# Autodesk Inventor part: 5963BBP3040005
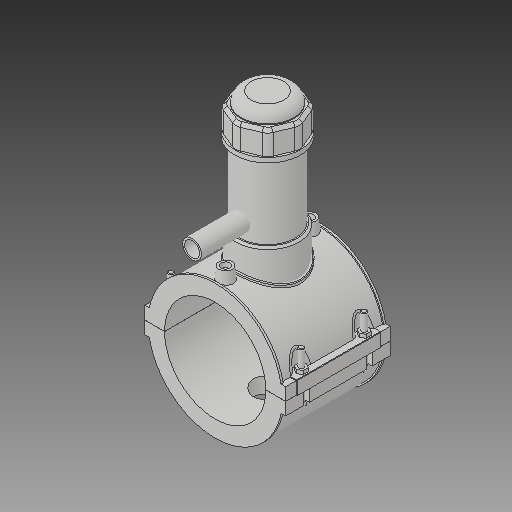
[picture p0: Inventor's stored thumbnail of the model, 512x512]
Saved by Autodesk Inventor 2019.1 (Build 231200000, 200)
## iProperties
Created: 2017-07
Part Number: 5963BBP3040005
Material: Generic
Description: PLASSON TAPPING SADDLE 4''IPS x 1/2''IPS
Document SubType Name: Modeling
Designer: KIM
Density: 1 g/cm^3
Appearance: Default
Author: KIM
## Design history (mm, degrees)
derived "5963BBP_5963BUP.ipt"
feature "Solid1::5963BBP_5963BUP.ipt"
feature "Solid2::5963BBP_5963BUP.ipt"
feature "Solid3::5963BBP_5963BUP.ipt"
tag "TaggingFeature1"
body "Solid1"
body "Solid2"
body "Solid3"
other parameters: "d0" = 114.1, "d2" = 159.004, "d3" = 28.525, "d4" = 118.11, "d5" = 0, "d6" = 0.1, "d8" = 0, "d19" = 6, "d20" = 6, "d21" = 70.866, "d23" = 0, "d24" = 35.433, "d26" = 0, "d27" = 3, "d28" = 3, "d29" = 3, "d30" = 38.03333, "d31" = 6, "d32" = 0, "d33" = 0, "d34" = 0.6, "d40" = 77.1316, "d41" = 74.165, "d43" = 0, "d45" = 0, "d47" = 145.031, "d70" = 15, "d72" = 0, "d73" = 6, "d75" = 5, "d76" = 0, "d77" = 5.705, "d78" = 87.05, "d79" = 15, "d80" = 47.244, "d82" = 5 deg, "d84" = 4, "d85" = 14, "d86" = 0, "d87" = 3, "d88" = 0, "d89" = 1, "d90" = 1, "d91" = 94.488, "d92" = 0, "d93" = 0.5, "d94" = 60.05263, "d96" = 151.2966, "d97" = 2.3622, "d98" = 0, "d102" = 1.141, "d120" = 140 deg, "d121" = 24.228, "d122" = 20 deg, "d123" = 296.66, "d124" = 88.998, "d126" = 0, "d143" = 117.523, "d145" = 26.33077, "d149" = 1.7115, "d150" = 28.96385, "d153" = 118.11, "d154" = 0, "d156" = 74.165, "d157" = 160 deg, "d159" = 6.846, "d161" = 1.7115, "d162" = 70.866, "d163" = 0, "d164" = 57.05, "d167" = 11.41, "d168" = 72.3561, "d170" = 3.2805, "d172" = 0, "d173" = 1, "d175" = 57.05, "d176" = 20 deg, "d177" = 7.987, "d178" = 34.23, "d180" = 0, "d183" = 13.692, "d184" = 6.3896, "d185" = 38.38575, "d186" = 38.38575, "d187" = 74.165, "d188" = 10.269, "d189" = 7.987, "d190" = 0, "d191" = 111.2475, "d193" = 6.9984, "d194" = 4.13385, "d195" = 90 deg, "d197" = 0, "d199" = 0, "d200" = 17.115, "d202" = 0, "d203" = 177.038, "d204" = 70.45675, "d205" = 51.9155, "d206" = 63.04025, "d207" = 132.7785, "d208" = 138.08964, "d209" = 164.64534, "d210" = 63.7819, "d211" = 74.165, "d212" = 59.332, "d213" = 48.9816, "d216" = 0, "d217" = 11.41, "d218" = 11.41, "d219" = 2.282, "d222" = 114.1, "d224" = 0, "d225" = 65.024, "d226" = 21.2, "d227" = 16.96, "d228" = 85.09, "d230" = 3.423, "d_" = 114.1, "B_" = 159.004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
